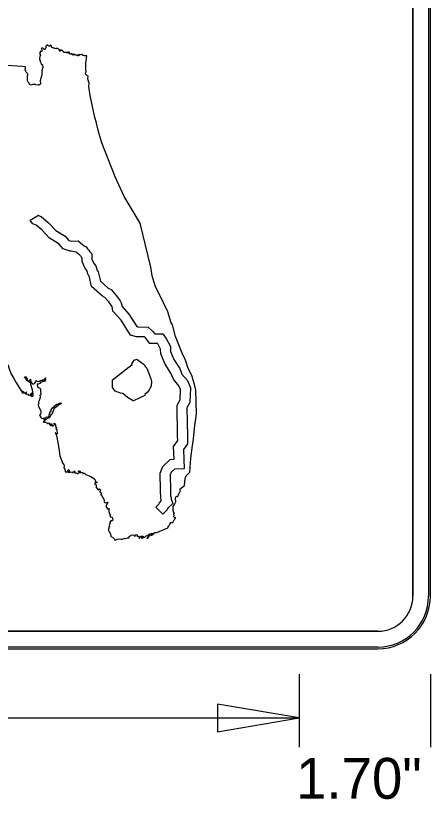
# Model space of a CAD drawing. Extents: x 0 to 770, y 0 to 495.
# Drawn here: x 413.9 to 449.5, y 21.7 to 88.9 of the extents above; entities that cross this region are included whole.
import ezdxf

# ---------------------------------------------------------------- set-up
doc = ezdxf.new("R2010")
doc.units = 0
for name, color, linetype in [('Dimension', 7, 'Continuous'), ('GSBWFill', 7, 'Continuous'), ('GSColorFill', 7, 'Continuous'), ('GSDims', 7, 'Continuous'), ('GSOutline', 7, 'Continuous'), ('SupstrConc', 7, 'Continuous')]:
    doc.layers.add(name, color=color, linetype=linetype)

msp = doc.modelspace()

# ---------------------------------------------------------------- linework, layer by layer
at = {"layer": 'Dimension'}
msp.add_lwpolyline([(438.218, 28.696), (431.201, 29.885), (431.201, 27.507)], close=True, dxfattribs=at)
at = {"layer": 'GSBWFill'}
for p, q in [((447.968, 138.123), (447.968, 39.123)), ((449.468, 39.123), (449.468, 138.123)), ((444.968, 36.123), (363.983, 36.123)), ((363.983, 34.623), (444.968, 34.623))]:
    msp.add_line(p, q, dxfattribs=at)
for radius in [4.5, 3]:
    msp.add_arc((444.968, 39.123), radius, 270, 0, dxfattribs=at)
at = {"layer": 'GSColorFill'}
for p, q in [((447.968, 138.123), (447.968, 39.123)), ((449.318, 138.123), (449.318, 39.123)), ((449.468, 39.123), (449.468, 138.123)), ((449.468, 39.123), (449.468, 138.123)), ((449.468, 39.123), (449.468, 138.123)), ((444.968, 36.123), (363.983, 36.123)), ((363.968, 34.623), (444.968, 34.623)), ((444.968, 34.773), (363.969, 34.773)), ((363.969, 34.623), (444.968, 34.623)), ((363.983, 34.623), (444.968, 34.623))]:
    msp.add_line(p, q, dxfattribs=at)
for radius in [4.5, 4.5, 3, 4.5, 4.35]:
    msp.add_arc((444.968, 39.123), radius, 270, 0, dxfattribs=at)
at = {"layer": 'GSDims'}
for p, q in [((438.218, 32.446), (438.218, 26.196)), ((438.218, 32.446), (438.218, 26.196)), ((449.468, 32.446), (449.468, 26.196)), ((370.718, 28.696), (438.218, 28.696))]:
    msp.add_line(p, q, dxfattribs=at)
at = {"layer": 'GSOutline'}
for p, q in [((447.968, 39.123), (447.968, 138.123)), ((449.468, 39.123), (449.468, 138.123)), ((363.968, 36.123), (444.968, 36.123)), ((363.968, 34.623), (444.968, 34.623))]:
    msp.add_line(p, q, dxfattribs=at)
for radius in [4.5, 3]:
    msp.add_arc((444.968, 39.123), radius, 270, 0, dxfattribs=at)
at = {"layer": 'SupstrConc'}
for p, q in [((419.861, 83.921), (419.954, 84.071)), ((422.428, 75.082), (421.282, 78.007)), ((423.213, 73.399), (422.428, 75.082)), ((424.565, 71.103), (423.213, 73.399)), ((415.138, 71.366), (415.861, 71.8)), ((415.861, 71.8), (415.879, 71.77)), ((415.879, 71.77), (415.895, 71.747)), ((415.895, 71.747), (416.093, 71.67)), ((416.093, 71.67), (416.711, 71.14)), ((415.653, 70.936), (415.351, 71.052)), ((416.711, 71.14), (417.335, 70.488)), ((418.682, 69.564), (419.242, 69.594)), ((419.079, 68.631), (418.645, 68.718)), ((420.001, 67.061), (419.838, 67.274)), ((420.971, 66.939), (421.163, 66.13)), ((421.163, 66.13), (421.831, 65.54)), ((421.351, 64.838), (420.404, 65.675)), ((421.548, 64.736), (421.351, 64.838)), ((421.882, 64.366), (421.548, 64.736)), ((422.542, 64.893), (422.853, 64.452)), ((423.608, 63.321), (424.291, 62.239)), ((425.03, 61.271), (424.932, 61.355)), ((425.402, 60.804), (425.03, 61.271)), ((426.088, 60.783), (425.402, 60.804)), ((426.095, 60.774), (426.088, 60.783)), ((426.705, 59.034), (426.338, 59.917)), ((423.855, 59.051), (424.059, 59.354)), ((424.059, 59.354), (424.291, 59.452)), ((424.291, 59.452), (424.903, 58.995)), ((422.21, 57.666), (423.616, 58.791)), ((423.616, 58.791), (423.714, 58.812)), ((423.714, 58.812), (423.799, 58.946)), ((423.799, 58.946), (423.89, 58.925)), ((423.89, 58.925), (423.855, 59.051)), ((424.903, 58.995), (425.036, 58.791)), ((425.036, 58.791), (425.156, 58.679)), ((425.156, 58.679), (425.198, 58.545)), ((425.198, 58.545), (425.493, 57.764)), ((427.968, 58.65), (428.16, 58.168)), ((413.899, 57.49), (414.391, 56.71)), ((422.21, 57.033), (422.21, 57.666)), ((425.528, 57.174), (425.346, 56.794)), ((425.493, 57.764), (425.55, 57.539)), ((425.55, 57.539), (425.528, 57.174)), ((427.899, 57.177), (427.429, 57.725)), ((422.428, 56.71), (422.21, 57.033)), ((422.885, 56.541), (422.428, 56.71)), ((423.089, 56.513), (422.885, 56.541)), ((423.482, 56.168), (423.089, 56.513)), ((425.198, 56.611), (424.987, 56.429)), ((425.346, 56.794), (425.198, 56.611)), ((423.975, 55.866), (423.482, 56.168)), ((424.987, 56.429), (424.987, 56.388)), ((424.987, 56.388), (424.987, 56.348)), ((427.446, 51.974), (427.798, 52.467)), ((427.798, 52.467), (427.789, 52.832)), ((428.633, 52.852), (428.633, 52.852)), ((428.633, 52.852), (428.648, 52.205)), ((427.476, 50.867), (427.446, 51.974)), ((427.507, 50.024), (427.237, 49.771)), ((428.342, 50.053), (427.507, 50.024)), ((425.924, 46.763), (426.179, 47.013)), ((426.515, 46.161), (425.924, 46.763))]:
    msp.add_line(p, q, dxfattribs=at)
for points in [[(416.472, 86.22), (416.493, 86.185), (416.493, 86.157), (416.493, 86.136), (416.458, 86.122), (416.437, 86.086), (416.423, 86.037), (416.423, 86.023), (416.388, 86.002), (416.374, 86.002), (416.317, 86.037), (416.268, 86.072), (416.212, 86.1), (416.198, 86.122), (416.163, 86.1), (416.135, 86.1), (416.135, 86.086), (416.1, 86.086), (416.078, 86.072), (416.1, 86.037), (416.135, 85.988), (416.163, 85.939), (416.163, 85.904), (416.135, 85.868), (416.078, 85.833), (416.029, 85.819), (416.015, 85.854), (415.994, 85.854), (415.98, 85.784), (415.98, 85.77), (415.98, 85.735), (415.98, 85.721), (415.945, 85.672), (415.945, 85.65), (415.98, 85.636), (415.994, 85.615), (415.994, 85.566), (416.015, 85.496), (415.98, 85.461), (415.966, 85.461), (415.966, 85.447), (415.966, 85.411), (415.98, 85.376), (415.966, 85.376), (415.966, 85.327), (415.931, 85.257), (415.931, 85.229), (415.945, 85.193), (415.931, 85.172), (415.931, 85.123), (415.98, 85.074), (415.994, 85.025), (415.98, 84.99), (416.029, 84.905), (416.05, 84.87), (416.05, 84.849), (416.064, 84.849), (416.078, 84.8), (416.078, 84.75), (416.1, 84.75), (416.149, 84.715), (416.184, 84.617), (416.212, 84.547), (416.212, 84.448), (416.198, 84.378), (416.163, 84.279), (416.135, 84.23), (416.149, 84.153), (416.163, 84.075), (416.149, 84.019), (416.149, 83.935), (416.149, 83.858), (416.149, 83.787), (416.114, 83.738), (416.114, 83.689), (416.078, 83.654), (416.078, 83.583), (416.015, 83.513), (416.029, 83.393), (416.029, 83.379), (415.98, 83.344), (415.98, 83.274), (416.015, 83.14), (416.015, 83.077), (416.015, 83.028), (415.945, 82.979), (415.882, 82.957)], [(418.364, 85.7), (418.328, 85.7), (418.3, 85.7), (418.265, 85.721), (418.265, 85.735), (418.244, 85.749), (418.23, 85.749), (418.195, 85.735), (418.167, 85.749), (418.146, 85.749), (418.11, 85.749), (418.096, 85.735), (418.082, 85.735), (418.061, 85.749), (418.047, 85.749), (417.998, 85.784), (417.998, 85.805), (417.998, 85.819), (417.928, 85.833), (417.928, 85.854), (417.949, 85.868), (417.928, 85.89), (417.892, 85.904), (417.843, 85.918), (417.808, 85.953), (417.808, 85.967), (417.759, 85.967), (417.745, 85.967), (417.745, 85.953), (417.731, 85.918), (417.745, 85.89), (417.667, 85.868), (417.653, 85.868), (417.667, 85.904), (417.639, 85.939), (417.653, 85.953), (417.604, 86.037), (417.583, 86.051), (417.569, 86.037), (417.569, 86.023), (417.52, 86.072), (417.485, 86.086), (417.45, 86.072), (417.421, 86.072), (417.386, 86.051), (417.386, 86.072), (417.351, 86.072), (417.288, 86.051), (417.288, 86.072), (417.288, 86.086), (417.288, 86.1), (417.253, 86.086), (417.203, 86.122), (417.098, 86.1), (417.098, 86.136), (417.084, 86.136), (417.007, 86.157), (417.007, 86.185), (416.992, 86.206), (416.992, 86.248), (416.978, 86.262), (416.943, 86.297), (416.943, 86.347), (416.929, 86.347), (416.908, 86.361), (416.894, 86.382), (416.873, 86.382), (416.859, 86.361), (416.845, 86.361), (416.859, 86.325), (416.859, 86.311), (416.859, 86.297), (416.845, 86.297), (416.775, 86.297), (416.711, 86.297), (416.711, 86.311), (416.676, 86.325), (416.676, 86.347), (416.655, 86.347), (416.655, 86.361), (416.655, 86.382), (416.641, 86.361), (416.606, 86.382), (416.606, 86.361), (416.571, 86.382), (416.472, 86.297), (416.493, 86.276), (416.493, 86.262), (416.493, 86.248), (416.472, 86.22)], [(420.009, 85.447), (419.84, 85.447), (419.791, 85.461), (419.7, 85.475), (419.671, 85.496), (419.636, 85.524), (419.615, 85.566), (419.587, 85.566), (419.467, 85.545), (419.418, 85.545), (419.348, 85.566), (419.299, 85.566), (419.299, 85.545), (419.299, 85.524), (419.299, 85.475), (419.299, 85.461), (419.264, 85.447), (419.235, 85.461), (419.214, 85.496), (419.214, 85.51), (419.186, 85.51), (419.165, 85.51), (419.13, 85.475), (419.116, 85.475), (419.102, 85.496), (419.102, 85.51), (419.081, 85.524), (419.039, 85.545), (419.01, 85.566), (418.975, 85.566), (418.94, 85.566), (418.926, 85.545), (418.891, 85.524), (418.877, 85.524), (418.891, 85.587), (418.877, 85.601), (418.842, 85.615), (418.821, 85.601), (418.821, 85.545), (418.807, 85.51), (418.792, 85.51), (418.771, 85.545), (418.757, 85.566), (418.722, 85.566), (418.708, 85.566), (418.708, 85.601), (418.722, 85.615), (418.722, 85.65), (418.687, 85.672), (418.673, 85.65), (418.673, 85.615), (418.659, 85.601), (418.638, 85.615), (418.624, 85.65), (418.603, 85.636), (418.589, 85.615), (418.553, 85.601), (418.525, 85.601), (418.504, 85.636), (418.504, 85.672), (418.525, 85.721), (418.504, 85.721), (418.49, 85.721), (418.469, 85.721), (418.455, 85.735), (418.455, 85.749), (418.469, 85.77), (418.455, 85.805), (418.42, 85.784), (418.364, 85.784), (418.328, 85.77), (418.314, 85.749), (418.328, 85.735), (418.35, 85.735), (418.385, 85.749), (418.406, 85.749), (418.406, 85.721), (418.385, 85.686), (418.364, 85.7)], [(419.954, 84.071), (419.925, 84.23), (419.91, 84.533), (419.925, 84.835), (420.009, 85.447)], [(414.722, 84.508), (414.461, 84.533), (413.139, 84.617), (412.049, 84.68), (410.903, 84.75), (409.582, 84.814), (408.499, 84.87), (407.43, 84.94), (405.841, 85.011), (405.7, 85.011), (404.751, 85.074)], [(415.882, 82.957), (415.86, 82.957), (415.832, 82.943), (415.635, 82.957), (415.586, 83.007), (415.523, 83.007), (415.474, 82.993), (415.439, 83.007), (415.354, 82.993), (415.27, 82.957), (415.199, 82.943), (415.15, 82.979), (415.101, 83.028), (415.052, 83.063), (415.038, 83.112), (415.017, 83.14), (415.003, 83.175), (414.96, 83.197), (414.925, 83.26), (414.911, 83.358), (414.897, 83.429), (414.897, 83.478), (414.911, 83.604), (414.897, 83.689), (414.911, 83.773), (414.925, 83.787), (414.925, 83.822), (414.946, 83.872), (414.925, 83.907), (414.862, 83.991), (414.792, 84.054), (414.757, 84.104), (414.742, 84.188), (414.693, 84.265), (414.693, 84.329), (414.728, 84.364), (414.728, 84.434), (414.722, 84.508)], [(420.114, 83.358), (420.093, 83.513), (420.114, 83.717), (420.093, 83.752), (419.96, 83.787), (419.946, 83.836), (419.861, 83.921)], [(420.822, 79.701), (420.691, 80.166), (420.276, 82.043), (420.178, 82.817), (420.206, 83.051)], [(415.351, 71.052), (415.171, 71.31), (415.138, 71.366)], [(416.8, 69.828), (416.131, 70.526), (415.653, 70.936)], [(426.569, 64.275), (425.852, 65.752), (425.613, 66.603), (425.479, 67.327), (424.565, 71.103)], [(417.335, 70.488), (418.15, 69.984), (418.443, 69.638), (418.682, 69.564)], [(418.645, 68.718), (418.56, 68.718), (417.958, 68.905), (417.592, 69.337), (416.8, 69.828)], [(419.242, 69.594), (419.615, 69.283), (419.758, 69.16), (419.927, 69.068), (420.049, 68.913), (420.168, 68.787), (420.252, 68.653)], [(419.371, 68.409), (419.274, 68.462), (419.079, 68.631)], [(420.252, 68.653), (420.416, 68.477), (420.439, 68.034), (420.609, 67.654)], [(419.589, 68.126), (419.581, 68.135), (419.498, 68.267), (419.409, 68.361), (419.371, 68.409)], [(419.838, 67.274), (419.605, 67.835), (419.589, 68.126)], [(420.609, 67.654), (420.762, 67.454), (420.883, 67.064), (420.971, 66.939)], [(420.404, 65.675), (420.187, 66.586), (420.116, 66.687), (420.001, 67.061)], [(421.831, 65.54), (422.072, 65.416), (422.542, 64.893)], [(422.935, 62.807), (422.232, 63.574), (422.157, 63.974), (422.151, 63.984), (421.882, 64.366)], [(422.853, 64.452), (422.957, 64.288), (423.017, 63.966), (423.608, 63.321)], [(427.61, 61.4), (427.342, 62.384), (427.23, 62.574), (426.949, 63.516), (426.569, 64.275)], [(424.932, 61.355), (424.246, 61.373), (423.747, 61.518), (422.935, 62.807)], [(424.291, 62.239), (424.377, 62.213), (425.251, 62.191), (425.64, 61.861), (425.819, 61.635), (426.518, 61.614), (426.815, 61.221), (427.162, 60.527), (427.176, 60.099)], [(428.524, 59.206), (428.404, 59.501), (428.242, 59.811), (427.61, 61.4)], [(426.338, 59.917), (426.325, 60.314), (426.095, 60.774)], [(427.176, 60.099), (427.454, 59.432), (427.968, 58.65)], [(413.006, 59.438), (413.02, 59.424), (413.069, 59.318), (413.09, 59.234), (413.252, 58.911), (413.308, 58.707), (413.491, 58.236), (413.73, 57.8), (413.899, 57.49)], [(429.36, 56.78), (429.255, 57.174), (429.037, 57.968), (428.664, 58.742), (428.524, 59.206)], [(427.429, 57.725), (427.216, 58.258), (426.705, 59.034)], [(415.389, 56.443), (415.34, 56.808), (415.185, 57.286), (415.185, 57.406), (415.003, 57.539), (414.841, 57.61), (414.792, 57.715), (414.792, 57.764), (414.707, 57.863), (414.644, 57.933), (414.757, 57.947), (414.827, 57.898), (414.841, 57.8), (414.876, 57.779), (414.876, 57.764), (414.862, 57.68), (414.982, 57.589), (415.15, 57.624), (415.136, 57.666), (415.15, 57.729), (415.199, 57.68), (415.199, 57.638), (415.185, 57.638), (415.171, 57.589), (415.235, 57.49), (415.235, 57.504), (415.284, 57.49), (415.235, 57.455), (415.368, 57.322), (415.502, 57.357), (415.621, 57.504), (415.607, 57.589), (415.678, 57.589), (415.727, 57.539), (415.86, 57.575), (415.945, 57.539), (415.98, 57.525), (415.994, 57.525), (415.994, 57.554), (416.064, 57.638), (416.149, 57.624), (416.233, 57.68), (416.247, 57.666), (416.233, 57.666), (416.247, 57.638), (416.332, 57.68), (416.374, 57.729), (416.437, 57.779), (416.437, 57.814), (416.472, 57.863), (416.437, 57.75), (416.409, 57.694), (416.437, 57.638), (416.493, 57.694), (416.437, 57.624), (416.36, 57.539), (416.212, 57.525), (416.163, 57.504), (416.064, 57.441), (416.05, 57.455), (416.029, 57.42), (415.98, 57.357), (415.86, 57.322), (415.811, 57.336), (415.748, 57.272), (415.776, 57.089), (415.846, 57.033), (415.966, 57.005), (416.015, 56.864), (416.015, 56.745), (416.05, 56.731), (416.015, 56.675), (416.064, 56.492)], [(428.16, 58.168), (428.623, 57.629), (428.894, 57), (428.842, 55.731), (428.585, 55.293), (428.633, 52.852)], [(427.789, 52.832), (427.736, 55.515), (428.008, 55.977), (428.043, 56.843), (427.899, 57.177)], [(414.391, 56.71), (414.51, 56.527), (414.51, 56.513), (414.524, 56.527), (414.51, 56.562), (414.51, 56.576), (414.461, 56.647), (414.426, 56.696), (414.44, 56.731), (414.489, 56.696), (414.595, 56.647), (414.574, 56.611), (414.623, 56.597), (414.693, 56.527), (414.827, 56.647), (414.757, 56.541), (414.792, 56.478), (414.757, 56.492), (414.728, 56.478), (414.792, 56.443), (414.813, 56.457), (414.876, 56.478), (414.925, 56.443), (414.982, 56.457), (415.003, 56.443), (414.946, 56.393), (415.003, 56.358), (415.101, 56.393), (415.136, 56.393), (415.122, 56.379), (415.101, 56.379), (415.101, 56.344), (415.171, 56.323), (415.185, 56.478), (415.284, 56.576), (415.305, 56.541), (415.256, 56.443), (415.235, 56.323), (415.284, 56.253), (415.368, 56.267), (415.403, 56.323), (415.389, 56.443)], [(416.064, 56.492), (416.029, 56.323), (415.966, 56.379), (415.98, 56.168), (415.917, 55.915), (415.846, 55.782), (415.882, 55.683), (415.86, 55.634), (415.811, 55.543), (415.846, 55.388), (416.029, 55.086), (416.064, 54.917), (416.029, 54.713), (415.98, 54.699), (415.945, 54.643), (416.078, 54.411), (416.149, 54.375), (416.374, 54.411), (416.521, 54.446), (416.542, 54.495), (416.592, 54.509), (416.725, 54.481), (416.725, 54.53), (416.859, 54.931), (416.943, 54.973), (416.929, 55.121), (417.049, 55.275), (417.084, 55.339), (417.133, 55.339), (417.154, 55.325), (417.168, 55.325), (417.168, 55.36), (417.168, 55.374), (417.203, 55.36), (417.217, 55.36), (417.203, 55.409), (417.421, 55.592), (417.52, 55.606), (417.653, 55.683), (417.667, 55.662), (417.78, 55.697), (417.829, 55.662), (417.731, 55.606), (417.689, 55.634), (417.667, 55.606), (417.667, 55.592), (417.267, 55.289), (417.154, 55.191), (417.035, 54.776), (416.978, 54.699), (416.894, 54.643), (416.845, 54.509), (416.789, 54.481), (416.76, 54.397), (416.676, 54.397), (416.521, 54.277), (416.437, 54.277), (416.388, 54.361), (416.296, 54.312), (416.296, 54.263), (416.332, 54.263), (416.423, 54.136)], [(429.114, 52.364), (429.255, 53.75), (429.41, 54.776), (429.36, 56.78)], [(424.987, 56.348), (423.987, 55.872), (423.975, 55.866)], [(416.423, 54.136), (416.423, 54.122), (416.317, 54.101), (416.317, 54.136), (416.296, 54.136), (416.268, 54.087), (416.282, 54.066), (416.282, 54.038), (416.423, 54.038), (416.557, 54.003), (416.655, 53.932), (416.711, 53.932), (416.711, 53.954), (416.711, 53.968), (416.725, 53.982), (416.824, 53.904), (416.789, 53.848), (416.894, 53.75), (416.929, 53.785), (416.873, 53.834), (416.894, 53.848), (416.943, 53.904), (416.992, 53.904), (416.992, 53.785), (416.978, 53.771), (417.035, 53.736), (417.084, 53.736), (417.098, 53.785), (417.098, 53.771), (417.098, 53.75), (417.119, 53.75), (417.154, 53.75), (417.232, 53.883), (417.203, 53.918), (417.182, 53.954), (417.253, 53.904), (417.337, 53.75), (417.316, 53.736), (417.302, 53.665), (417.386, 53.616), (417.351, 53.475), (417.4, 53.426), (417.4, 53.44), (417.421, 53.426), (417.45, 53.025), (417.4, 53.054), (417.372, 53.039), (417.386, 53.054), (417.302, 53.138), (417.288, 53.173), (417.267, 53.159), (417.288, 53.138), (417.386, 52.92)], [(417.386, 52.92), (417.583, 51.816), (417.667, 51.155), (417.878, 50.663), (417.892, 50.6)], [(428.648, 52.205), (428.297, 51.714), (428.342, 50.053)], [(428.835, 49.751), (428.917, 50.958), (429.051, 52.055), (429.114, 52.364)], [(417.892, 50.6), (417.977, 50.466), (418.026, 50.445), (418.047, 50.209)], [(426.296, 49.669), (426.517, 50.252), (427.16, 50.856), (427.476, 50.867)], [(418.047, 50.209), (418.012, 50.171), (418.012, 50.121), (418.11, 50.023)], [(418.11, 50.023), (418.146, 49.925), (418.146, 49.805), (418.364, 49.805), (418.406, 49.819), (418.364, 49.925), (418.441, 50.002), (418.49, 49.939), (418.469, 49.889), (418.504, 49.84), (418.525, 49.819), (418.441, 49.77), (418.406, 49.77), (418.406, 49.756), (418.469, 49.735), (418.624, 49.77), (418.757, 49.784), (418.778, 49.786)], [(418.778, 49.786), (418.771, 49.77), (418.771, 49.735), (418.807, 49.707), (418.856, 49.756), (418.905, 49.784), (418.926, 49.889), (418.94, 49.868), (418.926, 49.805), (418.961, 49.784), (418.961, 49.735), (418.94, 49.721), (418.989, 49.671), (419.116, 49.707), (419.186, 49.636), (419.25, 49.636), (419.348, 49.735), (419.299, 49.819), (419.285, 49.819), (419.285, 49.868), (419.32, 49.854), (419.348, 49.868), (419.418, 49.84), (419.418, 49.805), (419.397, 49.805), (419.397, 49.735), (419.453, 49.735)], [(419.453, 49.735), (419.517, 49.735), (419.615, 49.756), (419.65, 49.707), (419.65, 49.622), (419.791, 49.671), (419.91, 49.566), (420.41, 49.376)], [(427.237, 49.771), (427.143, 49.521), (427.163, 48.232), (427.176, 47.723), (427.227, 47.601)], [(427.476, 46.043), (427.462, 46.184), (427.525, 46.247), (427.462, 46.268), (427.392, 46.451), (427.413, 46.824), (427.511, 46.993), (427.631, 47.211), (427.596, 47.506), (427.645, 47.639), (427.743, 47.703), (427.764, 47.654), (427.828, 47.752), (428.025, 48.195), (427.989, 48.314), (428.39, 48.631), (428.439, 49.207), (428.524, 49.446), (428.835, 49.751)], [(420.41, 49.376), (420.691, 49.158), (420.754, 48.961), (420.888, 48.891), (420.789, 48.842), (420.67, 48.856), (420.691, 48.764), (420.789, 48.687), (420.789, 48.448), (421.007, 48.23), (421.092, 48.329), (421.183, 48.251), (421.113, 48.075), (421.232, 48.005), (421.197, 47.787), (421.232, 47.857), (421.514, 47.33), (421.45, 47.309), (421.5, 47.196), (421.584, 47.147), (421.809, 47.196), (421.619, 46.824), (421.795, 46.585), (421.907, 46.655), (421.907, 46.599), (421.942, 46.571), (421.942, 46.55), (421.893, 46.571), (421.893, 46.402), (422.013, 46.043), (422.013, 45.924), (422.16, 45.91), (422.224, 45.643), (422.16, 45.586), (422.09, 45.621), (421.978, 45.474)], [(426.383, 47.434), (426.337, 47.546), (426.32, 48.215), (426.296, 49.669)], [(426.179, 47.013), (426.227, 47.136), (426.383, 47.292), (426.383, 47.434)], [(427.227, 47.601), (427.227, 47.447), (427.374, 47.09), (426.949, 46.665), (426.9, 46.538), (426.515, 46.161)], [(425.992, 44.588), (426.949, 44.996), (426.984, 45.031), (426.949, 45.066), (426.984, 45.143), (427.019, 45.129), (427.117, 45.312), (427.244, 45.439), (427.364, 45.453), (427.497, 45.671), (427.56, 45.72), (427.61, 45.875), (427.596, 45.889), (427.56, 45.839), (427.462, 45.938), (427.476, 46.043)], [(421.978, 45.474), (422.013, 45.453), (421.907, 45.2), (421.928, 45.143), (421.893, 45.045), (421.893, 44.982), (421.858, 44.897), (421.858, 44.743), (421.942, 44.651), (422.041, 44.454), (422.062, 44.321), (422.062, 44.25), (422.196, 44.201), (422.364, 44.011), (422.414, 43.941), (422.442, 43.941), (422.589, 44.011), (422.786, 44.046), (422.92, 44.011), (423.025, 44.011), (423.194, 44.082), (423.229, 44.068), (423.229, 44.082), (423.264, 44.103), (423.349, 44.082), (423.496, 44.131), (423.63, 44.131), (423.651, 44.187), (423.63, 44.271), (423.735, 44.3), (423.799, 44.37), (423.989, 44.384), (424.094, 44.335), (424.122, 44.271), (424.242, 44.335), (424.207, 44.405), (424.242, 44.433), (424.326, 44.405), (424.312, 44.286)], [(424.312, 44.286), (424.425, 44.286), (424.474, 44.187), (424.495, 44.131), (424.46, 44.103), (424.516, 44.117), (424.537, 44.131), (424.537, 44.166), (424.516, 44.215), (424.537, 44.271), (424.621, 44.236), (424.699, 44.117), (424.839, 44.131), (424.783, 44.187), (424.699, 44.187), (424.671, 44.271), (424.818, 44.286), (424.839, 44.25), (424.853, 44.201), (424.973, 44.187), (425.121, 44.321), (425.261, 44.286), (425.275, 44.236), (425.156, 44.103), (425.156, 44.082), (425.261, 44.152), (425.31, 44.215), (425.332, 44.3), (425.395, 44.335), (425.43, 44.335), (425.381, 44.349), (425.247, 44.335), (425.226, 44.37), (425.332, 44.454), (425.599, 44.539), (425.599, 44.468), (425.578, 44.384), (425.479, 44.384), (425.479, 44.37), (425.55, 44.349), (425.613, 44.405), (425.746, 44.504), (425.767, 44.588), (425.992, 44.588)]]:
    msp.add_lwpolyline(points, dxfattribs=at)
for points in [[(420.206, 83.051), (420.213, 83.095), (420.181, 83.191), (420.146, 83.267), (420.114, 83.358)], [(421.282, 78.007), (421.198, 78.293), (420.974, 79.032), (420.822, 79.701)]]:
    msp.add_open_spline(points, degree=2, dxfattribs=at)

# ---------------------------------------------------------------- texts
at = {"layer": 'GSDims'}
msp.add_text('1.70"', height=3.5, dxfattribs=at).set_placement((437.956, 21.765))

doc.saveas('drawing.dxf')
